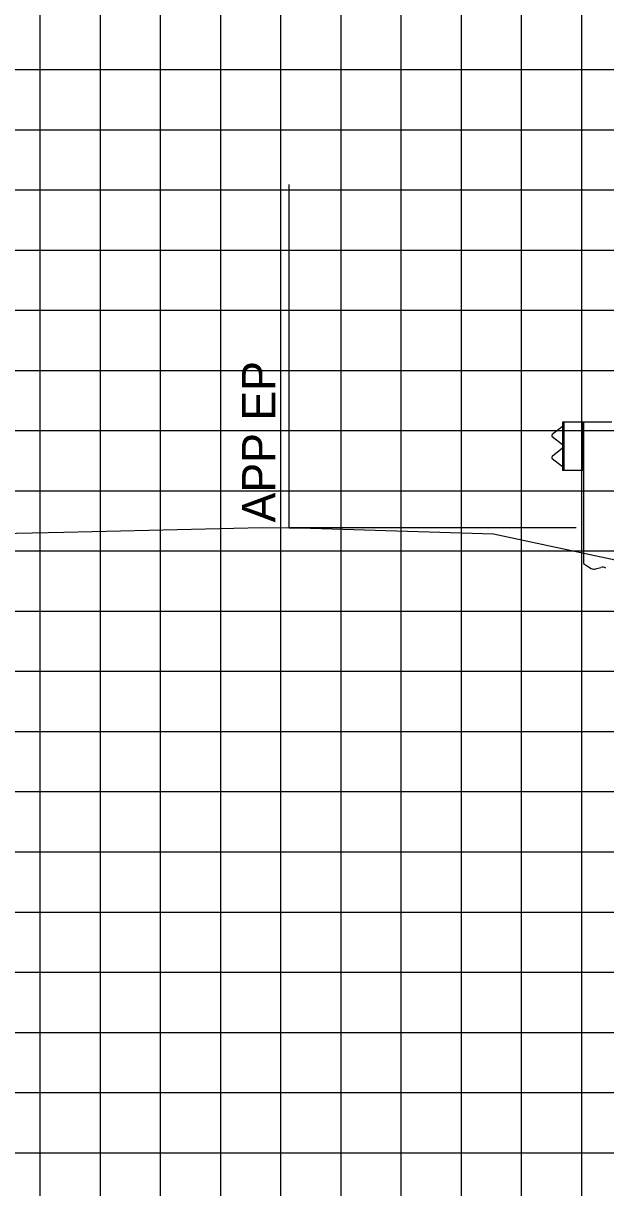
# Model space of a CAD drawing. Extents: x 1797809 to 2198143, y 249608 to 1237864.
# Drawn here: x 2194956.3 to 2194975.66, y 1237270.94 to 1237309.65 of the extents above; entities that cross this region are included whole.
import ezdxf

# ---------------------------------------------------------------- set-up
doc = ezdxf.new("R2010")
doc.units = 0
for name, color, linetype in [('29', 7, 'Continuous'), ('3', 7, 'Continuous'), ('DESIGN - SHEET - Light Grid', 7, 'Continuous'), ('GSDIMS', 7, 'Continuous'), ('GSSHT', 7, 'Continuous'), ('Level 55', 7, 'Continuous')]:
    doc.layers.add(name, color=color, linetype=linetype)

msp = doc.modelspace()

# ---------------------------------------------------------------- linework, layer by layer
at = {"layer": '29'}
for p, q in [((2194974.219, 1237296.248), (2194973.876, 1237295.974)), ((2194974.219, 1237296.386), (2194974.219, 1237294.779)), ((2194975.862, 1237296.386), (2194974.219, 1237296.386)), ((2194974.266, 1237296.386), (2194974.266, 1237294.779)), ((2194974.876, 1237296.386), (2194974.876, 1237294.779)), ((2194974.923, 1237296.386), (2194974.923, 1237291.686)), ((2194973.877, 1237295.909), (2194974.219, 1237295.647)), ((2194974.219, 1237295.518), (2194973.876, 1237295.244)), ((2194973.877, 1237295.178), (2194974.219, 1237294.917)), ((2194974.923, 1237294.779), (2194974.219, 1237294.779)), ((2194974.923, 1237291.686), (2194975.084, 1237291.577)), ((2194975.084, 1237291.577), (2194975.175, 1237291.528)), ((2194975.323, 1237291.511), (2194975.493, 1237291.558))]:
    msp.add_line(p, q, dxfattribs=at)
for centre, major_axis, start_param, end_param in [((2194973.909, 1237295.942), (-0.0469, 0), 5.497787, 7.096872), ((2194973.909, 1237295.212), (-0.0469, 0), 5.497787, 7.096872), ((2194975.27, 1237291.695), (-0.196, 0), 1.064721, 1.848328), ((2194975.547, 1237291.374), (-0.196, 0), 4.106844, 4.989921)]:
    msp.add_ellipse(centre, major_axis=major_axis, ratio=0.978687, start_param=start_param, end_param=end_param, dxfattribs=at)
at = {"layer": '3'}
msp.add_line((2194965.131, 1237292.876), (2194965.131, 1237304.291), dxfattribs=at)
at = {"layer": 'DESIGN - SHEET - Light Grid'}
msp.add_lwpolyline([(2194952.377, 1237292.616), (2194957.644, 1237292.736), (2194964.239, 1237292.883), (2194965.131, 1237292.876), (2194965.49, 1237292.879), (2194970.14, 1237292.734), (2194971.926, 1237292.676), (2194978.876, 1237291.196)], dxfattribs=at)
at = {"layer": 'GSDIMS'}
msp.add_line((2194974.671, 1237292.876), (2194965.131, 1237292.876), dxfattribs=at)
at = {"layer": 'GSSHT'}
for p, q in [((2194956.86, 1237258.106), (2194956.86, 1237318.106)), ((2194958.86, 1237258.106), (2194958.86, 1237318.106)), ((2194960.86, 1237258.106), (2194960.86, 1237318.106)), ((2194962.86, 1237258.106), (2194962.86, 1237318.106)), ((2194964.86, 1237258.106), (2194964.86, 1237318.106)), ((2194966.86, 1237258.106), (2194966.86, 1237318.106)), ((2194968.86, 1237258.106), (2194968.86, 1237318.106)), ((2194970.86, 1237258.106), (2194970.86, 1237318.106)), ((2194972.86, 1237258.106), (2194972.86, 1237318.106)), ((2194974.86, 1237258.106), (2194974.86, 1237318.106)), ((2194892.86, 1237308.106), (2195022.86, 1237308.106)), ((2194892.86, 1237306.106), (2195022.86, 1237306.106)), ((2194892.86, 1237304.106), (2195022.86, 1237304.106)), ((2194892.86, 1237302.106), (2195022.86, 1237302.106)), ((2194892.86, 1237300.106), (2195022.86, 1237300.106)), ((2194892.86, 1237298.106), (2195022.86, 1237298.106)), ((2194892.86, 1237296.106), (2195022.86, 1237296.106)), ((2194892.86, 1237294.106), (2195022.86, 1237294.106)), ((2194892.86, 1237292.106), (2195022.86, 1237292.106)), ((2194892.86, 1237290.106), (2195022.86, 1237290.106)), ((2194892.86, 1237288.106), (2195022.86, 1237288.106)), ((2194892.86, 1237286.106), (2195022.86, 1237286.106)), ((2194892.86, 1237284.106), (2195022.86, 1237284.106)), ((2194892.86, 1237282.106), (2195022.86, 1237282.106)), ((2194892.86, 1237280.106), (2195022.86, 1237280.106)), ((2194892.86, 1237278.106), (2195022.86, 1237278.106)), ((2194892.86, 1237276.106), (2195022.86, 1237276.106)), ((2194892.86, 1237274.106), (2195022.86, 1237274.106)), ((2194892.86, 1237272.106), (2195022.86, 1237272.106))]:
    msp.add_line(p, q, dxfattribs=at)

# ---------------------------------------------------------------- texts
at = {"layer": 'Level 55'}
msp.add_text('APP EP', height=1.1105, rotation=90, dxfattribs=at).set_placement((2194964.679, 1237293.054))

doc.saveas('drawing.dxf')
